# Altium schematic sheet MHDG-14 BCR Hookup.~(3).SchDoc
size B
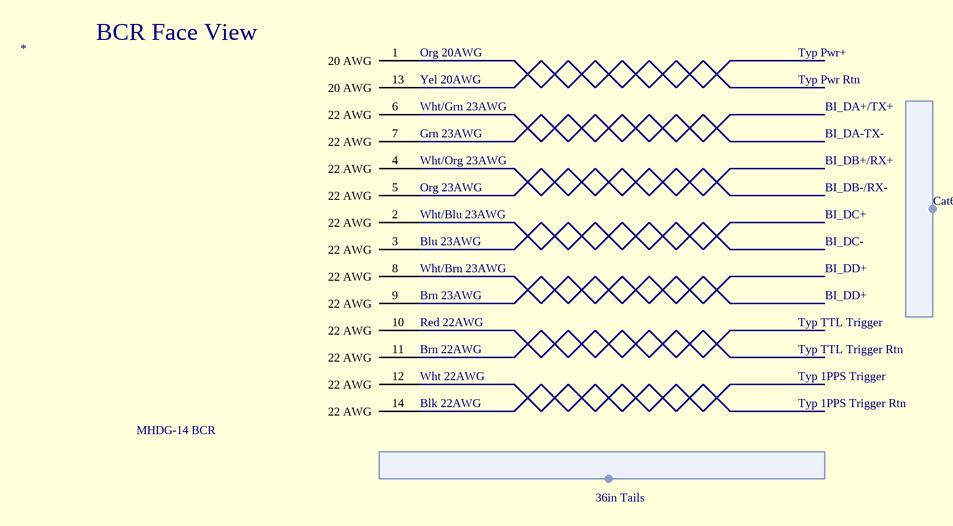
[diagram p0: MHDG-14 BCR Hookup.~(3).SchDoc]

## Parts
*  MHDG-14 BCR

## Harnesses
Cat6E wired to TIA/EIA 568A Standard: 
36in Tails: 

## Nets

Not connected (* = marked no-connect by the designer): * 1(20_AWG) 2(22_AWG) 3(22_AWG) 4(22_AWG) 5(22_AWG) 6(22_AWG) 7(22_AWG) 8(22_AWG) 9(22_AWG) 10(22_AWG) 11(22_AWG) 12(22_AWG) 13(20_AWG) 14(22_AWG)

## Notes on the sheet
- BCR Face View
- (near *) Org 20AWG
- Typ Pwr+
- (near *) Yel 20AWG
- (near *) Wht/Grn 23AWG
- (near *) Grn 23AWG
- Typ Pwr Rtn
- BI_DA+/TX+
- BI_DA-TX-
- (near *) Wht/Org 23AWG
- (near *) Org 23AWG
- BI_DB+/RX+
- BI_DB-/RX-
- (near *) Wht/Blu 23AWG
- (near *) Blu 23AWG
- (near *) Wht/Brn 23AWG
- BI_DC+
- BI_DC-
- BI_DD+
- (near *) Brn 23AWG
- (near *) Red 22AWG
- Typ TTL Trigger
- (near *) Brn 22AWG
- (near *) Wht 22AWG
- (near *) Blk 22AWG
- Typ TTL Trigger Rtn
- Typ 1PPS Trigger
- Typ 1PPS Trigger Rtn

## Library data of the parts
* = MHDG-14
